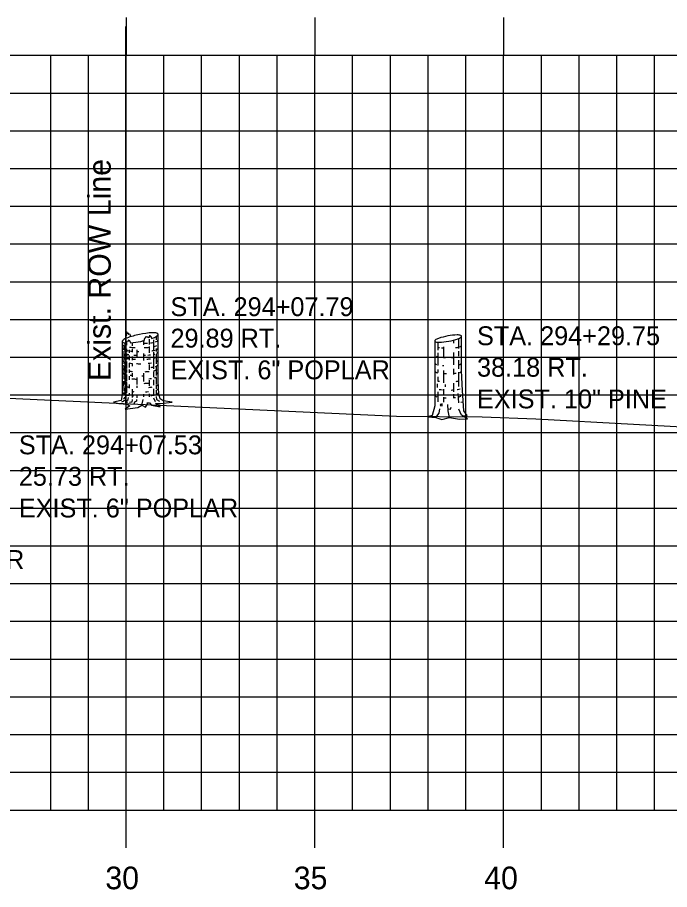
# Model space of a CAD drawing. Extents: x 859129 to 859299, y 366268 to 366378.
# Drawn here: x 859239.58 to 859256.86, y 366335.13 to 366358.24 of the extents above; entities that cross this region are included whole.
import ezdxf

# ---------------------------------------------------------------- set-up
doc = ezdxf.new("R2010")
doc.units = 0
for name, color, linetype in [('D_Text_Monospaced', 7, 'Continuous'), ('E_ROW_Line', 7, 'Continuous'), ('H_V ANNOTATION', 7, 'Continuous'), ('MAJOR', 7, 'Continuous'), ('MINOR', 7, 'Continuous'), ('S_Roadway_Centerline', 7, 'Continuous'), ('S_Trees_Conifer_NonPay', 7, 'Continuous'), ('S_Trees_Decid_NonPay', 7, 'Continuous')]:
    doc.layers.add(name, color=color, linetype=linetype)

msp = doc.modelspace()

# ---------------------------------------------------------------- linework, layer by layer
at = {"layer": 'E_ROW_Line'}
msp.add_line((859242.453, 366348.002), (859242.453, 366358.002), dxfattribs=at)
at = {"layer": 'MAJOR'}
for p, q in [((859242.462, 366358.238), (859242.462, 366357.236)), ((859247.462, 366358.238), (859247.462, 366357.236)), ((859252.462, 366358.238), (859252.462, 366357.236)), ((859142.462, 366357.236), (859282.462, 366357.236)), ((859142.462, 366357.236), (859282.462, 366357.236)), ((859242.462, 366337.236), (859242.462, 366357.236)), ((859247.462, 366337.236), (859247.462, 366357.236)), ((859252.462, 366337.236), (859252.462, 366357.236)), ((859142.462, 366352.236), (859282.462, 366352.236)), ((859142.462, 366347.236), (859282.462, 366347.236)), ((859142.462, 366342.236), (859282.462, 366342.236)), ((859142.462, 366337.236), (859282.462, 366337.236)), ((859142.462, 366337.236), (859282.462, 366337.236)), ((859242.462, 366336.234), (859242.462, 366337.236)), ((859247.462, 366336.234), (859247.462, 366337.236)), ((859252.462, 366336.234), (859252.462, 366337.236))]:
    msp.add_line(p, q, dxfattribs=at)
at = {"layer": 'MINOR'}
for p, q in [((859240.462, 366337.236), (859240.462, 366357.236)), ((859241.462, 366337.236), (859241.462, 366357.236)), ((859243.462, 366337.236), (859243.462, 366357.236)), ((859244.462, 366337.236), (859244.462, 366357.236)), ((859245.462, 366337.236), (859245.462, 366357.236)), ((859246.462, 366337.236), (859246.462, 366357.236)), ((859248.462, 366337.236), (859248.462, 366357.236)), ((859249.462, 366337.236), (859249.462, 366357.236)), ((859250.462, 366337.236), (859250.462, 366357.236)), ((859251.462, 366337.236), (859251.462, 366357.236)), ((859253.462, 366337.236), (859253.462, 366357.236)), ((859254.462, 366337.236), (859254.462, 366357.236)), ((859255.462, 366337.236), (859255.462, 366357.236)), ((859256.462, 366337.236), (859256.462, 366357.236)), ((859142.462, 366356.236), (859282.462, 366356.236)), ((859142.462, 366355.236), (859282.462, 366355.236)), ((859142.462, 366354.236), (859282.462, 366354.236)), ((859142.462, 366353.236), (859282.462, 366353.236)), ((859142.462, 366351.236), (859282.462, 366351.236)), ((859142.462, 366350.236), (859282.462, 366350.236)), ((859142.462, 366349.236), (859282.462, 366349.236)), ((859142.462, 366348.236), (859282.462, 366348.236)), ((859142.462, 366346.236), (859282.462, 366346.236)), ((859142.462, 366345.236), (859282.462, 366345.236)), ((859142.462, 366344.236), (859282.462, 366344.236)), ((859142.462, 366343.236), (859282.462, 366343.236)), ((859142.462, 366341.236), (859282.462, 366341.236)), ((859142.462, 366340.236), (859282.462, 366340.236)), ((859142.462, 366339.236), (859282.462, 366339.236)), ((859142.462, 366338.236), (859282.462, 366338.236))]:
    msp.add_line(p, q, dxfattribs=at)
at = {"layer": 'S_Roadway_Centerline'}
msp.add_lwpolyline([(859229.051, 366348.623), (859249.622, 366347.669), (859251.895, 366347.658), (859253.318, 366347.598), (859263.668, 366347.033)], dxfattribs=at)
at = {"layer": 'S_Trees_Conifer_NonPay'}
for p, q in [((859250.716, 366349.631), (859250.716, 366349.425)), ((859251.134, 366349.686), (859251.134, 366349.607)), ((859250.716, 366349.352), (859250.716, 366349.021)), ((859250.873, 366349.506), (859250.873, 366349.232)), ((859251.134, 366349.358), (859251.134, 366349.032)), ((859251.269, 366349.397), (859251.269, 366349.266)), ((859251.269, 366349.158), (859251.269, 366348.931)), ((859250.716, 366348.907), (859250.716, 366348.828)), ((859250.873, 366348.879), (859250.873, 366348.56)), ((859251.134, 366348.931), (859251.134, 366348.778)), ((859251.269, 366348.839), (859251.269, 366348.463)), ((859250.716, 366348.714), (859250.716, 366348.604)), ((859250.699, 366348.527), (859250.699, 366348.43)), ((859250.873, 366348.39), (859250.873, 366348.231)), ((859250.914, 366348.516), (859250.914, 366348.446)), ((859251.134, 366348.549), (859251.134, 366348.316)), ((859250.716, 366348.316), (859250.716, 366348.048)), ((859250.873, 366348.173), (859250.873, 366348.042)), ((859251.134, 366348.253), (859251.134, 366348.167)), ((859251.251, 366348.27), (859251.268, 366348.025)), ((859251.329, 366348.042), (859251.39, 366348.049))]:
    msp.add_line(p, q, dxfattribs=at)
for points in [[(859251.38, 366347.681), (859251.496, 366347.69), (859251.404, 366347.816), (859251.371, 366348.356), (859251.35, 366348.873), (859251.35, 366349.793)], [(859250.637, 366349.665), (859250.637, 366347.947), (859250.567, 366347.69), (859250.448, 366347.656), (859250.665, 366347.64), (859250.824, 366347.581), (859251.033, 366347.64), (859251.296, 366347.593), (859251.502, 366347.598), (859251.35, 366347.702), (859251.279, 366347.855)], [(859251.269, 366349.726), (859251.269, 366349.629), (859251.269, 366349.465)], [(859250.796, 366348.003), (859250.785, 366347.958), (859250.835, 366347.947), (859250.835, 366348.009)], [(859251.033, 366347.64), (859250.989, 366347.816), (859250.983, 366347.98)], [(859250.987, 366347.866), (859251.056, 366347.86), (859251.075, 366347.913)], [(859250.665, 366347.64), (859250.755, 366347.752), (859250.772, 366347.866)]]:
    msp.add_lwpolyline(points, dxfattribs=at)
for centre, radius, start, end in [((859251.31, 366348.002), 1.825, 100.3798, 108.3946), ((859251.31, 366348.002), 1.825, 92.3651, 100.3798), ((859251.244, 366349.581), 0.245, 70.3798, 92.3651), ((859251.176, 366349.954), 0.245, 288.3946, 310.3798), ((859251.302, 366349.743), 0.0729, 59.1402, 70.3798), ((859251.288, 366349.822), 0.0729, 310.3798, 321.6195), ((859251.326, 366349.783), 0.0263, 40.3798, 59.1402), ((859251.324, 366349.793), 0.0263, 321.6195, 340.3798), ((859251.332, 366349.788), 0.0186, 26.433, 40.3798), ((859251.336, 366349.79), 0.0141, 10.3798, 26.433), ((859251.332, 366349.791), 0.0186, 340.3798, 354.3267), ((859251.336, 366349.79), 0.0141, 354.3267, 10.3798), ((859250.656, 366349.664), 0.0186, 160.3798, 174.3267), ((859250.651, 366349.665), 0.0141, 174.3267, 190.3798), ((859250.651, 366349.665), 0.0141, 190.3798, 206.433), ((859250.663, 366349.662), 0.0263, 141.6195, 160.3798), ((859250.655, 366349.667), 0.0186, 206.433, 220.3798), ((859250.652, 366349.549), 0.0143, 180, 196.0515), ((859250.661, 366349.672), 0.0263, 220.3798, 239.1402), ((859250.699, 366349.633), 0.0729, 130.3798, 141.6195), ((859250.685, 366349.712), 0.0729, 239.1402, 250.3798), ((859250.811, 366349.502), 0.245, 108.3946, 130.3798), ((859250.743, 366349.874), 0.245, 250.3798, 272.3651), ((859250.678, 366351.453), 1.825, 272.3651, 280.3798), ((859250.678, 366351.453), 1.825, 280.3798, 288.3946), ((859251.294, 366349.59), 0.0738, 300, 311.2506), ((859251.325, 366349.554), 0.0267, 311.2506, 330), ((859251.332, 366349.55), 0.0189, 330, 343.9485), ((859250.779, 366349.738), 0.245, 254.8461, 261.8968), ((859250.994, 366351.245), 1.767, 261.8968, 262.605), ((859250.994, 366351.245), 1.767, 264.3267, 266.0499), ((859250.994, 366351.245), 1.767, 276.2449, 278.1032), ((859251.209, 366349.738), 0.245, 278.1032, 284.1859), ((859251.209, 366349.738), 0.245, 291.7653, 300), ((859250.652, 366349.083), 0.0143, 180, 196.0515), ((859250.656, 366349.084), 0.0189, 196.0515, 210), ((859250.663, 366349.088), 0.0267, 210, 228.7494), ((859250.694, 366349.124), 0.0738, 228.7494, 240), ((859250.781, 366349.485), 0.245, 244.3148, 257.5375), ((859250.996, 366350.993), 1.767, 265.8991, 267.5962), ((859250.996, 366350.993), 1.767, 272.7221, 274.4847), ((859251.294, 366349.124), 0.0738, 300, 311.2506), ((859251.325, 366349.088), 0.0267, 311.2506, 330), ((859251.327, 366349.302), 0.0267, 311.2506, 330), ((859251.332, 366349.084), 0.0189, 330, 343.9485), ((859251.334, 366349.298), 0.0189, 330, 343.9485), ((859250.652, 366348.872), 0.0143, 180, 196.0515), ((859250.656, 366348.873), 0.0189, 196.0515, 210), ((859250.663, 366348.877), 0.0267, 210, 228.7494), ((859250.694, 366348.912), 0.0738, 228.7494, 240), ((859250.779, 366349.271), 0.245, 240, 246.7914), ((859250.78, 366349.06), 0.245, 240, 254.9514), ((859250.779, 366349.271), 0.245, 254.8461, 257.5454), ((859250.994, 366350.779), 1.767, 265.2285, 266.1325), ((859251.209, 366349.271), 0.245, 284.1859, 300), ((859251.209, 366349.06), 0.245, 292.1924, 300), ((859251.294, 366348.912), 0.0738, 300, 311.2506), ((859251.325, 366348.877), 0.0267, 311.2506, 330), ((859251.332, 366348.873), 0.0189, 330, 343.9485), ((859250.779, 366348.841), 0.245, 254.9814, 261.8968), ((859250.994, 366350.568), 1.767, 266.0429, 268.5525), ((859250.994, 366350.568), 1.767, 274.5361, 277.0026), ((859251.208, 366348.841), 0.245, 278.1032, 284.3207), ((859250.651, 366348.435), 0.0143, 180, 196.0515), ((859250.994, 366350.348), 1.767, 261.8968, 262.45), ((859250.994, 366350.131), 1.767, 262.2622, 265.0496), ((859250.994, 366350.348), 1.767, 276.7966, 278.1032), ((859250.994, 366350.131), 1.767, 277.63, 278.1032), ((859251.208, 366348.624), 0.245, 278.1032, 294.6056), ((859250.651, 366348.229), 0.0143, 180, 196.0515), ((859250.655, 366348.231), 0.0189, 196.0515, 210), ((859250.662, 366348.235), 0.0267, 210, 228.7494), ((859250.693, 366348.27), 0.0738, 228.7494, 240), ((859250.778, 366348.418), 0.245, 240, 249.1675), ((859250.993, 366349.925), 1.767, 266.0862, 268.2187), ((859250.994, 366350.131), 1.767, 272.6293, 274.5612), ((859250.993, 366349.925), 1.767, 274.2776, 276.3006), ((859251.208, 366348.418), 0.245, 284.0684, 300), ((859251.293, 366348.27), 0.0738, 300, 302.05)]:
    msp.add_arc(centre, radius, start, end, dxfattribs=at)
at = {"layer": 'S_Trees_Decid_NonPay'}
for p, q in [((859243.255, 366349.786), (859243.255, 366349.691)), ((859242.397, 366349.543), (859242.397, 366349.461)), ((859242.424, 366349.613), (859242.424, 366349.395)), ((859242.467, 366349.608), (859242.467, 366349.556)), ((859242.624, 366349.618), (859242.624, 366349.539)), ((859242.921, 366349.67), (859242.921, 366349.564)), ((859243.068, 366349.716), (859243.068, 366349.568)), ((859243.187, 366349.699), (859243.187, 366349.399)), ((859242.397, 366349.391), (859242.397, 366349.261)), ((859242.424, 366349.326), (859242.424, 366349.174)), ((859242.467, 366349.453), (859242.467, 366349.37)), ((859242.467, 366349.335), (859242.467, 366349.261)), ((859242.537, 366349.434), (859242.537, 366349.348)), ((859242.624, 366349.453), (859242.624, 366349.368)), ((859242.742, 366349.434), (859242.742, 366349.234)), ((859242.921, 366349.335), (859242.921, 366349.249)), ((859243.068, 366349.52), (859243.068, 366349.352)), ((859243.187, 366349.37), (859243.187, 366349.239)), ((859243.255, 366349.465), (859243.255, 366349.382)), ((859243.255, 366349.313), (859243.255, 366349.062)), ((859242.397, 366349.239), (859242.397, 366349.057)), ((859242.424, 366349.069), (859242.424, 366348.991)), ((859242.467, 366349.234), (859242.467, 366349.174)), ((859242.467, 366349.121), (859242.467, 366348.94)), ((859242.537, 366349.277), (859242.537, 366349.156)), ((859242.537, 366349.081), (859242.537, 366348.966)), ((859242.624, 366349.257), (859242.624, 366349.156)), ((859242.624, 366349.071), (859242.624, 366348.995)), ((859242.921, 366349.214), (859242.921, 366349.144)), ((859243.187, 366349.205), (859243.187, 366348.924)), ((859242.397, 366349.01), (859242.397, 366348.763)), ((859242.424, 366348.964), (859242.424, 366348.858)), ((859242.467, 366348.909), (859242.467, 366348.827)), ((859242.537, 366348.905), (859242.537, 366348.823)), ((859243.068, 366349.045), (859243.068, 366348.897)), ((859243.187, 366348.854), (859243.187, 366348.709)), ((859243.255, 366348.979), (859243.255, 366348.749)), ((859242.397, 366348.744), (859242.397, 366348.65)), ((859242.424, 366348.823), (859242.424, 366348.722)), ((859242.424, 366348.696), (859242.424, 366348.514)), ((859242.467, 366348.773), (859242.467, 366348.602)), ((859242.537, 366348.736), (859242.537, 366348.639)), ((859242.624, 366348.81), (859242.624, 366348.713)), ((859242.742, 366348.697), (859242.742, 366348.51)), ((859242.921, 366348.81), (859242.921, 366348.588)), ((859243.068, 366348.627), (859243.068, 366348.474)), ((859243.187, 366348.639), (859243.187, 366348.497)), ((859243.255, 366348.678), (859243.255, 366348.518)), ((859242.395, 366348.596), (859242.396, 366348.337)), ((859242.424, 366348.411), (859242.424, 366348.219)), ((859242.467, 366348.569), (859242.467, 366348.289)), ((859242.537, 366348.51), (859242.537, 366348.411)), ((859242.624, 366348.388), (859242.624, 366348.164)), ((859242.742, 366348.479), (859242.742, 366348.426)), ((859243.187, 366348.396), (859243.187, 366348.215)), ((859243.255, 366348.501), (859243.255, 366348.396)), ((859242.426, 366348.172), (859242.391, 366348.121)), ((859242.397, 366348.298), (859242.397, 366348.224)), ((859242.467, 366348.237), (859242.467, 366348.211)), ((859242.537, 366348.281), (859242.537, 366348.223)), ((859242.742, 366348.25), (859242.742, 366348.159)), ((859242.921, 366348.254), (859242.921, 366348.188)), ((859243.068, 366348.262), (859243.068, 366348.184)), ((859243.188, 366348.155), (859243.229, 366348.059)), ((859243.255, 366348.359), (859243.255, 366348.235)), ((859242.344, 366348.05), (859242.411, 366348.081)), ((859242.881, 366347.968), (859242.916, 366348.114))]:
    msp.add_line(p, q, dxfattribs=at)
for points in [[(859242.356, 366349.65), (859242.356, 366348.238), (859242.333, 366348.09), (859242.13, 366348.046), (859242.27, 366348.011), (859242.488, 366347.993), (859242.558, 366347.949), (859242.436, 366347.861), (859242.768, 366347.904), (859242.881, 366347.968), (859242.974, 366347.908), (859243.03, 366347.987), (859243.021, 366348.024), (859243.083, 366348.025), (859243.135, 366347.968), (859243.367, 366347.917), (859243.24, 366348.005), (859243.371, 366348.007), (859243.68, 366348.045), (859243.441, 366348.075), (859243.363, 366348.133), (859243.324, 366348.254), (859243.307, 366348.608), (859243.307, 366349.842)], [(859242.451, 366349.731), (859242.455, 366349.825), (859242.469, 366349.798), (859242.469, 366349.92), (859242.49, 366349.856), (859242.505, 366349.889), (859242.521, 366349.833), (859242.537, 366349.85), (859242.556, 366349.842), (859242.575, 366349.775)], [(859242.943, 366349.676), (859242.952, 366349.743), (859242.976, 366349.747), (859242.984, 366349.782), (859243.015, 366349.768), (859243.03, 366349.782), (859243.054, 366349.759), (859243.077, 366349.768), (859243.089, 366349.817), (859243.097, 366349.774), (859243.128, 366349.782), (859243.131, 366349.731)], [(859242.473, 366349.607), (859242.49, 366349.669), (859242.513, 366349.657), (859242.543, 366349.691), (859242.577, 366349.613)], [(859242.474, 366348.081), (859242.517, 366348.116), (859242.525, 366348.164)], [(859243.258, 366348.193), (859243.266, 366348.116), (859243.345, 366348.067)], [(859242.395, 366348.098), (859242.474, 366348.081), (859242.49, 366348.038)], [(859242.621, 366348.116), (859242.616, 366348.046), (859242.552, 366348.034)], [(859242.733, 366348.11), (859242.733, 366348.073), (859242.682, 366348.043), (859242.665, 366347.993)]]:
    msp.add_lwpolyline(points, dxfattribs=at)
for centre, radius, start, end in [((859243.326, 366347.383), 2.507, 101.8277, 109.7098), ((859243.326, 366347.383), 2.507, 93.9457, 101.8277), ((859243.176, 366349.563), 0.322, 71.8277, 93.9457), ((859243.074, 366350.051), 0.322, 289.7098, 311.8277), ((859243.247, 366349.78), 0.0935, 60.604, 71.8277), ((859243.226, 366349.881), 0.0935, 311.8277, 323.0514), ((859243.276, 366349.833), 0.0336, 41.8277, 60.604), ((859243.274, 366349.845), 0.0336, 323.0514, 341.8277), ((859243.284, 366349.839), 0.0237, 27.8832, 41.8277), ((859243.289, 366349.842), 0.0179, 11.8277, 27.8832), ((859243.283, 366349.842), 0.0237, 341.8277, 355.7722), ((859243.289, 366349.842), 0.0179, 355.7722, 11.8277), ((859242.38, 366349.65), 0.0237, 161.8277, 175.7722), ((859242.374, 366349.65), 0.0179, 175.7722, 191.8277), ((859242.374, 366349.65), 0.0179, 191.8277, 207.8832), ((859242.389, 366349.647), 0.0336, 143.0514, 161.8277), ((859242.376, 366349.581), 0.0191, 173.8872, 180), ((859242.376, 366349.581), 0.0191, 180, 196.0515), ((859242.379, 366349.653), 0.0237, 207.8832, 221.8277), ((859242.382, 366349.583), 0.0252, 196.0515, 210), ((859242.391, 366349.588), 0.0356, 210, 228.7494), ((859242.386, 366349.66), 0.0336, 221.8277, 240.604), ((859242.437, 366349.611), 0.0935, 131.8277, 143.0514), ((859242.432, 366349.635), 0.0984, 228.7494, 240), ((859242.416, 366349.712), 0.0935, 240.604, 251.8277), ((859242.589, 366349.441), 0.322, 109.7098, 131.8277), ((859242.546, 366349.832), 0.326, 240, 248.0494), ((859242.487, 366349.929), 0.322, 251.8277, 267.5521), ((859242.337, 366352.109), 2.507, 275.4987, 281.8277), ((859242.337, 366352.109), 2.507, 281.8277, 284.0013), ((859242.832, 366351.956), 2.356, 272.1614, 274.76), ((859242.832, 366351.956), 2.356, 276.7201, 278.1032), ((859242.337, 366352.109), 2.507, 288.4719, 289.7098), ((859243.118, 366349.946), 0.326, 278.1032, 282.1964), ((859243.118, 366349.832), 0.326, 282.1964, 299.0901), ((859243.118, 366349.946), 0.326, 291.6757, 300), ((859243.232, 366349.749), 0.0984, 300, 311.2506), ((859243.274, 366349.701), 0.0356, 311.2506, 330), ((859243.283, 366349.696), 0.0252, 330, 343.9485), ((859243.289, 366349.694), 0.0191, 0, 16.0515), ((859243.289, 366349.694), 0.0191, 343.9485, 0), ((859242.376, 366349.48), 0.0191, 173.8872, 180), ((859242.376, 366349.48), 0.0191, 180, 196.0515), ((859242.376, 366349.377), 0.0191, 173.8872, 180), ((859242.376, 366349.377), 0.0191, 180, 196.0515), ((859242.382, 366349.482), 0.0252, 196.0515, 210), ((859242.391, 366349.487), 0.0356, 210, 228.7494), ((859242.432, 366349.534), 0.0984, 228.7494, 240), ((859242.546, 366349.732), 0.326, 240, 248.0494), ((859242.546, 366349.629), 0.326, 255.9618, 261.8968), ((859242.546, 366349.732), 0.326, 260.9146, 261.8968), ((859242.832, 366351.742), 2.356, 261.8968, 264.9353), ((859242.832, 366351.639), 2.356, 261.8968, 262.6162), ((859242.832, 366351.843), 2.356, 263.2266, 266.8519), ((859242.832, 366351.742), 2.356, 267.8019, 269.1881), ((859242.832, 366351.843), 2.356, 272.6327, 275.758), ((859242.832, 366351.639), 2.356, 275.0054, 276.6587), ((859242.832, 366351.742), 2.356, 277.4481, 278.1032), ((859243.118, 366349.732), 0.326, 278.1032, 289.5833), ((859243.118, 366349.629), 0.326, 282.1964, 288.3169), ((859243.118, 366349.732), 0.326, 296.4281, 300), ((859243.118, 366349.629), 0.326, 296.757, 300), ((859243.232, 366349.534), 0.0984, 300, 311.2506), ((859243.232, 366349.431), 0.0984, 300, 311.2506), ((859243.274, 366349.487), 0.0356, 311.2506, 330), ((859243.274, 366349.384), 0.0356, 311.2506, 330), ((859243.283, 366349.482), 0.0252, 330, 343.9485), ((859243.283, 366349.379), 0.0252, 330, 343.9485), ((859243.289, 366349.48), 0.0191, 0, 16.0515), ((859243.289, 366349.48), 0.0191, 343.9485, 0), ((859243.289, 366349.377), 0.0191, 0, 16.0515), ((859243.289, 366349.377), 0.0191, 343.9485, 0), ((859242.376, 366349.272), 0.0191, 173.8872, 180), ((859242.376, 366349.272), 0.0191, 180, 196.0515), ((859242.376, 366349.157), 0.0191, 173.8872, 180), ((859242.376, 366349.157), 0.0191, 180, 196.0515), ((859242.382, 366349.274), 0.0252, 196.0515, 210), ((859242.382, 366349.159), 0.0252, 196.0515, 210), ((859242.391, 366349.279), 0.0356, 210, 228.7494), ((859242.391, 366349.164), 0.0356, 210, 228.7494), ((859242.432, 366349.326), 0.0984, 228.7494, 240), ((859242.432, 366349.211), 0.0984, 228.7494, 240), ((859242.546, 366349.524), 0.326, 240, 248.0494), ((859242.546, 366349.409), 0.326, 240, 255.9618), ((859242.546, 366349.524), 0.326, 255.9618, 261.8968), ((859242.832, 366351.534), 2.356, 261.8968, 262.8132), ((859242.832, 366351.419), 2.356, 262.8132, 264.9353), ((859242.832, 366351.534), 2.356, 264.9353, 266.9933), ((859242.832, 366351.639), 2.356, 266.0259, 267.8019), ((859242.832, 366351.639), 2.356, 272.1614, 273.4964), ((859242.832, 366351.534), 2.356, 274.3638, 276.7318), ((859242.832, 366351.419), 2.356, 275.2089, 277.3412), ((859243.118, 366349.524), 0.326, 282.1964, 294.8455), ((859243.118, 366349.409), 0.326, 294.8455, 300), ((859243.232, 366349.211), 0.0984, 300, 311.2506), ((859243.274, 366349.164), 0.0356, 311.2506, 330), ((859243.283, 366349.159), 0.0252, 330, 343.9485), ((859243.289, 366349.157), 0.0191, 0, 16.0515), ((859243.289, 366349.157), 0.0191, 343.9485, 0), ((859242.375, 366349.043), 0.0191, 173.8872, 180), ((859242.375, 366349.043), 0.0191, 180, 196.0515), ((859242.381, 366349.045), 0.0252, 196.0515, 210), ((859242.376, 366348.838), 0.0191, 173.8872, 180), ((859242.376, 366348.838), 0.0191, 180, 196.0515), ((859242.39, 366349.05), 0.0356, 210, 228.7494), ((859242.378, 366348.943), 0.0191, 173.8872, 180), ((859242.378, 366348.943), 0.0191, 180, 196.0515), ((859242.384, 366348.944), 0.0252, 196.0515, 210), ((859242.393, 366348.95), 0.0356, 210, 228.7494), ((859242.431, 366349.097), 0.0984, 228.7494, 240), ((859242.435, 366348.997), 0.0984, 228.7494, 240), ((859242.545, 366349.294), 0.326, 240, 242.9942), ((859242.548, 366349.194), 0.326, 240, 247.5951), ((859242.545, 366349.294), 0.326, 248.1902, 256.0964), ((859242.835, 366351.204), 2.356, 262.7545, 265.0266), ((859242.832, 366351.419), 2.356, 267.586, 270), ((859242.832, 366351.419), 2.356, 270, 270.4422), ((859242.835, 366351.204), 2.356, 273.1471, 275.6557), ((859242.831, 366351.304), 2.356, 277.1385, 278.1032), ((859243.118, 366349.294), 0.326, 278.1032, 282.3301), ((859243.121, 366349.194), 0.326, 283.0921, 300), ((859243.118, 366349.294), 0.326, 292.1344, 300), ((859243.231, 366349.097), 0.0984, 300, 311.2506), ((859243.273, 366349.05), 0.0356, 311.2506, 330), ((859243.282, 366349.045), 0.0252, 330, 343.9485), ((859243.288, 366349.043), 0.0191, 0, 16.0515), ((859243.288, 366349.043), 0.0191, 343.9485, 0), ((859243.289, 366348.838), 0.0191, 0, 16.0515), ((859243.289, 366348.838), 0.0191, 343.9485, 0), ((859243.291, 366348.943), 0.0191, 0, 16.0515), ((859242.376, 366348.747), 0.0191, 173.8872, 180), ((859242.382, 366348.84), 0.0252, 196.0515, 210), ((859242.391, 366348.845), 0.0356, 210, 228.7494), ((859242.432, 366348.892), 0.0984, 228.7494, 240), ((859242.546, 366349.089), 0.326, 240, 242.8475), ((859242.546, 366349.089), 0.326, 248.0494, 255.9618), ((859242.832, 366351.099), 2.356, 263.572, 264.9353), ((859242.832, 366351.009), 2.356, 264.7274, 267.8019), ((859242.832, 366351.099), 2.356, 270.9946, 272.1614), ((859242.832, 366351.009), 2.356, 275.5135, 277.4157), ((859243.118, 366348.999), 0.326, 286.0817, 298.061), ((859243.118, 366349.089), 0.326, 294.8455, 300), ((859243.232, 366348.892), 0.0984, 300, 311.2506), ((859243.274, 366348.845), 0.0356, 311.2506, 330), ((859243.283, 366348.84), 0.0252, 330, 343.9485), ((859242.38, 366348.519), 0.0191, 173.8872, 180), ((859242.38, 366348.519), 0.0191, 180, 196.0515), ((859242.386, 366348.521), 0.0252, 196.0515, 210), ((859242.395, 366348.526), 0.0356, 210, 228.7494), ((859242.436, 366348.573), 0.0984, 228.7494, 240), ((859242.555, 366348.66), 0.326, 240, 246.3456), ((859242.546, 366348.885), 0.326, 248.0494, 255.9618), ((859242.55, 366348.77), 0.326, 255.2259, 261.8968), ((859242.836, 366350.78), 2.356, 261.8968, 262.7137), ((859242.832, 366350.895), 2.356, 272.531, 275.758), ((859242.836, 366350.78), 2.356, 275.5148, 277.7774), ((859243.122, 366348.77), 0.326, 294.0625, 300), ((859243.127, 366348.66), 0.326, 298.0903, 300), ((859243.236, 366348.573), 0.0984, 300, 311.2506), ((859243.241, 366348.462), 0.0984, 300, 311.2506), ((859243.278, 366348.526), 0.0356, 311.2506, 330), ((859243.283, 366348.415), 0.0356, 311.2506, 330), ((859243.287, 366348.521), 0.0252, 330, 343.9485), ((859243.293, 366348.519), 0.0191, 0, 16.0515), ((859243.293, 366348.519), 0.0191, 343.9485, 0), ((859243.292, 366348.41), 0.0252, 330, 343.9485), ((859243.298, 366348.408), 0.0191, 0, 16.0515), ((859243.298, 366348.408), 0.0191, 343.9485, 0), ((859242.39, 366348.298), 0.0191, 173.8872, 180), ((859242.39, 366348.298), 0.0191, 180, 196.0515), ((859242.396, 366348.3), 0.0252, 196.0515, 210), ((859242.405, 366348.305), 0.0356, 210, 228.7494), ((859242.447, 366348.352), 0.0984, 228.7494, 240), ((859242.56, 366348.549), 0.326, 245.2906, 261.8968), ((859242.847, 366350.559), 2.356, 261.8968, 262.4597), ((859242.841, 366350.67), 2.356, 264.7171, 265.8136), ((859242.847, 366350.559), 2.356, 264.5833, 265.4449), ((859242.841, 366350.67), 2.356, 273.1842, 275.0911), ((859242.847, 366350.559), 2.356, 276.4667, 278.1032), ((859243.133, 366348.549), 0.326, 278.1032, 279.6166), ((859243.133, 366348.549), 0.326, 292.0839, 300), ((859243.247, 366348.352), 0.0984, 300, 311.2506), ((859243.288, 366348.305), 0.0356, 311.2506, 330), ((859243.297, 366348.3), 0.0252, 330, 343.9485), ((859243.303, 366348.298), 0.0191, 0, 16.0515), ((859243.303, 366348.298), 0.0191, 343.9485, 0)]:
    msp.add_arc(centre, radius, start, end, dxfattribs=at)

# ---------------------------------------------------------------- texts
at = {"layer": 'D_Text_Monospaced'}
for s, height, p in [('STA. 294+07.79', 0.49998, (859243.636, 366350.324)), ('29.89 RT.', 0.5, (859243.636, 366349.49)), ('STA. 294+29.75', 0.49998, (859251.758, 366349.553)), ('EXIST. 6" POPLAR', 0.49998, (859243.636, 366348.65)), ('38.18 RT.', 0.5, (859251.758, 366348.719)), ('EXIST. 10" PINE', 0.49998, (859251.758, 366347.879)), ('STA. 294+07.53', 0.49998, (859239.618, 366346.662)), ('25.73 RT.', 0.5, (859239.618, 366345.828)), ('EXIST. 6" POPLAR', 0.49998, (859239.618, 366344.988)), ('EXIST. 2" BOX ALDER', 0.49998, (859232.837, 366343.623))]:
    msp.add_text(s, height=height, dxfattribs=at).set_placement(p)
at = {"layer": 'E_ROW_Line'}
msp.add_text('Exist. ROW Line', height=0.6, rotation=90, dxfattribs=at).set_placement((859242.053, 366348.602))
at = {"layer": 'H_V ANNOTATION'}
for s, p in [('30', (859241.91, 366335.136)), ('35', (859246.902, 366335.136)), ('40', (859251.948, 366335.136))]:
    msp.add_text(s, height=0.6, dxfattribs=at).set_placement(p)

doc.saveas('drawing.dxf')
